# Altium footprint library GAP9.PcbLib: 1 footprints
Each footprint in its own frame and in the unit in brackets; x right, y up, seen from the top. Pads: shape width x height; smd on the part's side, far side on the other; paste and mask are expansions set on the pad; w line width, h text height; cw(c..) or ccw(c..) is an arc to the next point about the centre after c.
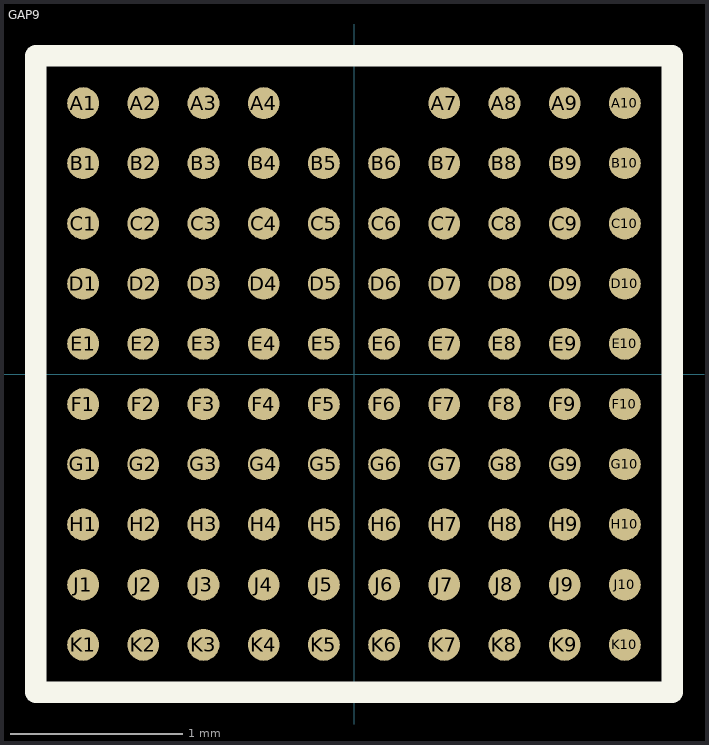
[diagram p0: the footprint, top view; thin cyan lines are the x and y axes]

## GAP9 [mm]
pads (98):
  round 0.185 smd paste-0.005 mask+0: A1(-1.575,1.575) A2(-1.225,1.575) A3(-0.875,1.575) A4(-0.525,1.575) A7(0.525,1.575) A8(0.875,1.575) A9(1.225,1.575) A10(1.575,1.575) B1(-1.575,1.225) B2(-1.225,1.225) B3(-0.875,1.225) B4(-0.525,1.225) B5(-0.175,1.225) B6(0.175,1.225) B7(0.525,1.225) B8(0.875,1.225) B9(1.225,1.225) B10(1.575,1.225) C1(-1.575,0.875) C2(-1.225,0.875) C3(-0.875,0.875) C4(-0.525,0.875) C5(-0.175,0.875) C6(0.175,0.875) C7(0.525,0.875) C8(0.875,0.875) C9(1.225,0.875) C10(1.575,0.875) D1(-1.575,0.525) D2(-1.225,0.525) D3(-0.875,0.525) D4(-0.525,0.525) D5(-0.175,0.525) D6(0.175,0.525) D7(0.525,0.525) D8(0.875,0.525) D9(1.225,0.525) D10(1.575,0.525) E1(-1.575,0.175) E2(-1.225,0.175) E3(-0.875,0.175) E4(-0.525,0.175) E5(-0.175,0.175) E6(0.175,0.175) E7(0.525,0.175) E8(0.875,0.175) E9(1.225,0.175) E10(1.575,0.175) F1(-1.575,-0.175) F2(-1.225,-0.175) F3(-0.875,-0.175) F4(-0.525,-0.175) F5(-0.175,-0.175) F6(0.175,-0.175) F7(0.525,-0.175) F8(0.875,-0.175) F9(1.225,-0.175) F10(1.575,-0.175) G1(-1.575,-0.525) G2(-1.225,-0.525) G3(-0.875,-0.525) G4(-0.525,-0.525) G5(-0.175,-0.525) G6(0.175,-0.525) G7(0.525,-0.525) G8(0.875,-0.525) G9(1.225,-0.525) G10(1.575,-0.525) H1(-1.575,-0.875) H2(-1.225,-0.875) H3(-0.875,-0.875) H4(-0.525,-0.875) H5(-0.175,-0.875) H6(0.175,-0.875) H7(0.525,-0.875) H8(0.875,-0.875) H9(1.225,-0.875) H10(1.575,-0.875) J1(-1.575,-1.225) J2(-1.225,-1.225) J3(-0.875,-1.225) J4(-0.525,-1.225) J5(-0.175,-1.225) J6(0.175,-1.225) J7(0.525,-1.225) J8(0.875,-1.225) J9(1.225,-1.225) J10(1.575,-1.225) K1(-1.575,-1.575) K2(-1.225,-1.575) K3(-0.875,-1.575) K4(-0.525,-1.575) K5(-0.175,-1.575) K6(0.175,-1.575) K7(0.525,-1.575) K8(0.875,-1.575) K9(1.225,-1.575) K10(1.575,-1.575)
Top Overlay:
  lines w0.127: -1.85,-1.85 -1.85,1.85 1.85,1.85 1.85,-1.85 -1.85,-1.85
3D body: height 0.52, standoff 0, extent -1.85,-1.85 1.85,1.85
